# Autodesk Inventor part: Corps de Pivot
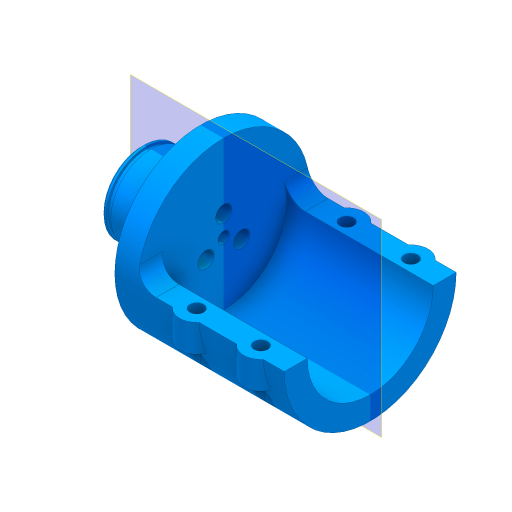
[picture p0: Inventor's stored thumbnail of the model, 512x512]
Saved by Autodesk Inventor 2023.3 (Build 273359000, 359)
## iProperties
Created: 2020-12
Part Number: Corps de Pivot
Material: Générique
Document SubType Name: Modeling
Designer: Joffre.gerschheimer
Density: 1 g/cm^3
Appearance: Par défaut(1)
Author: Joffre.gerschheimer
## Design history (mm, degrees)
sketch "Esquisse1"
  geometry: L1 (99.75, -37.5)-(25.75, -37.5); L2 (99.75, -37.5)-(99.75, 0); L3 (99.75, 0)-(0, 0); L4 (25.75, -37.5)-(25.75, 0); L5 (17.75, 0)-(17.75, -23.97); L6 (17.75, -23.97)-(25.75, -23.97); L7 (4, 0)-(4, -17.5); L8 (4, -17.5)-(17.75, -17.5); L9 (2, 0)-(2, -16.5); L10 (2, -16.5)-(4, -16.5); L11 (1, 0)-(1, -17.5); L12 (1, -17.5)-(2, -17.5); L13 (2, -16.5)-(2, -17.5); L14 (1, -16.5)-(0, -16.5); L15 (0, -16.5)-(0, 0); L16 (1, -16.5)-(1, -17.5); L17 (1, -17.5)-(0, -16.5); 1 further point
  constraints: 34 end point, 12 point on line, 8 perpendicular, 4 vertical, 2 horizontal, 1 coincident, 1 parallel
  dimensions: "d10" = 74 distance of L1.start L1.end; "d12" = 13.75 distance of L7.end L8.end; "d13" = 8 distance of L5.end L6.end; "d14" = 2 distance of L9.end L10.end; "d15" = 1 distance of L11.end L12.end; "d16" = 1 distance of L14.start L14.end; "d17" = 37.5 distance of L1.end L4.end; "d18" = 23.97 distance of L5.start L5.end; "d19" = 17.5 distance of L7.start L7.end; "d20" = 16.5 distance of L9.start L9.end; "d21" = 17.5 distance of L11.start L11.end (derived); "d22" = 16.5 distance of L14.end L3.end
revolve "Révolution1" sketch "Esquisse1" stored, may be unused: angle "d23" = 90 deg
sketch "Esquisse3"
  geometry: L1 (0, -37.5)-(0, 0); L2 (0, 0)-(0, 37.5); A1 r 37.5 centre (0, 0) between (0, -37.5) and (0, 37.5) reference; 1 further point
  constraints: 4 end point, 2 point on circle, 1 point on line, 1 vertical
extrude "Extrusion1" cut sketch "Esquisse3" distance "d24" = 64; taper "d25" = 0 deg
fillet "Congé1" dims "d26" = 8
sketch "Esquisse4"
  geometry: L1 (0, 37.5)-(0, -37.5) reference; C1 r 27.5 at (0, 0); 1 further point
  constraints: 1 centre point, 1 midpoint
  dimensions: "d27" = 55 diameter of C1
extrude "Extrusion2" cut sketch "Esquisse4" distance "d28" = 64; taper "d29" = 0 deg
fillet "Congé2" dims "d30" = 8
sketch "Esquisse5"
  geometry: L1 (0, 10)-(0, 0) reference; L2 (0, 0)-(-56, 0) reference; L3 (-7.505, 5.035)-(-22.495, 5.035); L4 (-64, 74.137)-(-64, 0.863) reference; A1 r 7.5 centre (-15, 4.755) between (-22.495, 5.035) and (-7.505, 5.035); 6 further points
  constraints: 2 end point, 2 midpoint, 2 point on circle, 1 centre point, 1 coincident
  dimensions: "d31" = 15 distance from line of L1 point (-15, 4.755); "d35" = 15 diameter of A1; "d87" = 32.465 vertical distance of point (-64, 37.5) point (-15, 5.035); "d100" = 4.755 distance from line of L2 point (-15, 4.755)
extrude "Extrusion3" join sketch "Esquisse5" distance "d37" = 12; taper "d38" = 0 deg
sketch "Esquisse10"
  geometry: 2 further points
hole "Perçage2" sketch "Esquisse10" at (0, 0) diameter "d68" = 4.917; stored, may be unused: countersink angle "d72" = 90 deg, drill point angle "d74" = 118 deg; dims "d69" = 12, "d70" = 4, "d71" = 2, "d73" = 8
sketch "Esquisse12"
  geometry: 1 further point
sketch "Esquisse13"
  geometry: 3 further points
  dimensions: "d76" = 9 distance of point (0, 0) point (9, 0)
hole "Perçage3" sketch "Esquisse13" at (9, 0) diameter "d77" = 7; stored, may be unused: countersink angle "d81" = 90 deg, drill point angle "d83" = 118 deg; dims "d78" = 6, "d79" = 9, "d80" = 2, "d82" = 8
pattern_circular "Réseau circulaire1" dims angle "d85" = 360 deg
sketch "Esquisse15"
  geometry: L1 (0, 65)-(0, 10) reference; C1 r 3 at (-15, 4.755); A1 r 7.5 centre (-15, 4.755) between (-20.8, 0) and (-9.2, 0) reference; 2 further points
  constraints: 1 centre point, 1 coincident, 1 midpoint
  dimensions: "d88" = 6 diameter of C1
extrude "Extrusion6" cut sketch "Esquisse15" extent not by distance; stored distance "d90" = 0; taper "d91" = 0 deg
sketch "Esquisse16"
  geometry: L1 (10.381, 4.755)-(12.691, 8.755); L2 (12.691, 8.755)-(17.309, 8.755); L3 (17.309, 8.755)-(19.619, 4.755); L4 (19.619, 4.755)-(17.309, 0.755); L5 (17.309, 0.755)-(12.691, 0.755); L6 (12.691, 0.755)-(10.381, 4.755); L7 (0, 10)-(0, 0) reference; A1 r 7.5 centre (15, 4.755) between (8.036, 1.972) and (21.964, 1.972) reference; 2 further points
  constraints: 12 end point, 1 coincident, 1 perpendicular, 13 other
  dimensions: "d92" = 8 distance between parallel lines of L2 L5
extrude "Extrusion7" cut sketch "Esquisse16" distance "d93" = 30; taper "d95" = 0 deg; dims "d94" = 5, "d96" = 0
pattern_linear "Réseau rectangulaire1" dims "d99" = 28
mirror "Symétrie2"
node "Solide1"
